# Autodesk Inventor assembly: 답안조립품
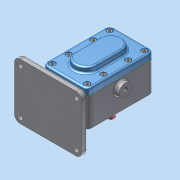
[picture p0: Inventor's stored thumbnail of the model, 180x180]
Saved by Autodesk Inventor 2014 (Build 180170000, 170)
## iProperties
Created: 2026-10
Part Number: 답안조립품
Document SubType Name: Assembly
Designer: dg
Author: dg
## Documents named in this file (12)
- C:\Users\dg\Desktop\761003V1008\답안조립품.iam
- C:\Users\dg\Desktop\761003V1008\본체.ipt
- C:\Users\dg\Desktop\761003V1008\가져온 구성요소\6각 구멍붙이 볼트 M5x16\6각 구멍붙이 볼트 M5x16.ipt
- C:\Users\dg\Desktop\761003V1008\가져온 구성요소\개스킷\개스킷.ipt
- C:\Users\dg\Desktop\761003V1008\가져온 구성요소\구동 축\구동 축.ipt
- C:\Users\dg\Desktop\761003V1008\가져온 구성요소\베어링 부시\베어링 부시.ipt
- C:\Users\dg\Desktop\761003V1008\가져온 구성요소\스퍼 기어\스퍼 기어.ipt
- C:\Users\dg\Desktop\761003V1008\가져온 구성요소\오일 실 16 28 7\오일 실 16 28 7.ipt
- C:\Users\dg\Desktop\761003V1008\가져온 구성요소\종동 축\종동 축.ipt
- C:\Users\dg\Desktop\761003V1008\가져온 구성요소\커버\커버.ipt
- C:\Users\dg\Desktop\761003V1008\가져온 구성요소\평행 키 6x6x18\평행 키 6x6x18.ipt
- C:\Users\dg\Desktop\761003V1008\가져온 구성요소\6각 구멍붙이 볼트 M5x16\6각 구멍붙이 볼트 M5x16_MIR.ipt
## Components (10 placed, 4 different names)
1. 6각 구멍붙이 볼트 M5x16:1
2. 개스킷:1
3. 구동 축:1
4. 6각 구멍붙이 볼트 M5x16:2
5. 6각 구멍붙이 볼트 M5x16:3
6. 6각 구멍붙이 볼트 M5x16:4
7. 6각 구멍붙이 볼트 M5x16_MIR:1
8. 6각 구멍붙이 볼트 M5x16_MIR:2
9. 6각 구멍붙이 볼트 M5x16_MIR:3
10. 6각 구멍붙이 볼트 M5x16_MIR:4
